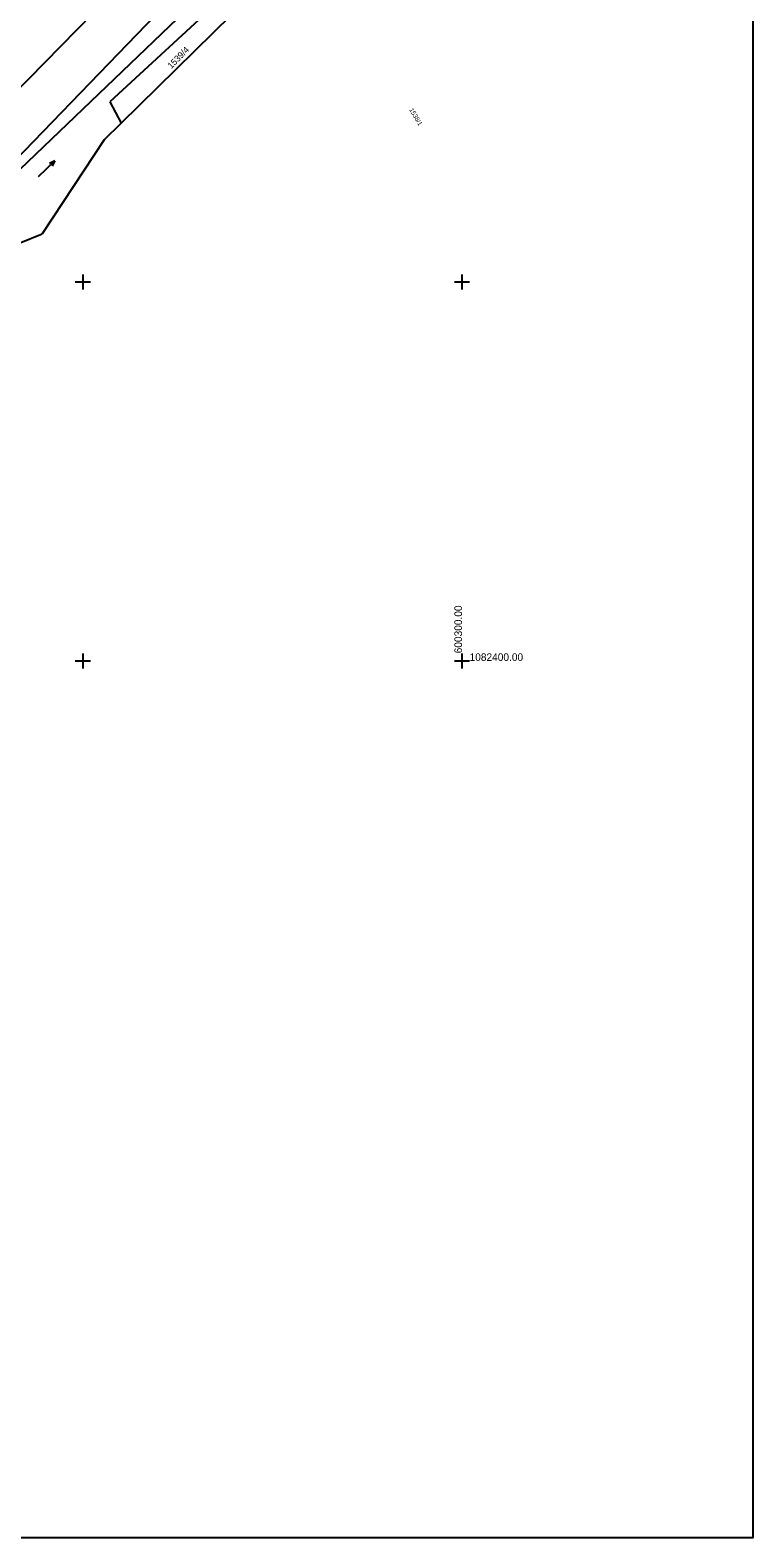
# Model space of a CAD drawing. Extents: x -601196 to -600262, y -1082523 to -1081922.
# Drawn here: x -600357 to -600261.6, y -1082515.7 to -1082316.8 of the extents above; entities that cross this region are included whole.
import ezdxf

# ---------------------------------------------------------------- set-up
doc = ezdxf.new("R2010")
doc.units = 0
for name, color, linetype in [('Vrstva 47', 7, 'Continuous'), ('Vrstva 59', 7, 'Continuous'), ('Vrstva 61', 7, 'Continuous'), ('Vrstva 63', 7, 'Continuous')]:
    doc.layers.add(name, color=color, linetype=linetype)

msp = doc.modelspace()

# ---------------------------------------------------------------- linework, layer by layer
at = {"layer": 'Vrstva 47'}
for p, q in [((-600420.14, -1082387.57), (-600313.5, -1082278.63)), ((-600321.42, -1082299.79), (-600375.67, -1082351.77)), ((-600320.22, -1082301.95), (-600346.46, -1082326.22)), ((-600344.96, -1082329.06), (-600320.08, -1082304.56)), ((-600333.37, -1082307.47), (-600365.05, -1082340.28)), ((-600346.46, -1082326.22), (-600344.96, -1082329.06)), ((-600347.2, -1082331.26), (-600344.96, -1082329.06)), ((-600347.2, -1082331.26), (-600355.38, -1082343.65)), ((-600355.85, -1082336.11), (-600353.71, -1082334.01)), ((-600353.71, -1082334.01), (-600354.42, -1082334.36)), ((-600353.71, -1082334.01), (-600354.07, -1082334.71)), ((-600366.11, -1082347.99), (-600355.38, -1082343.65))]:
    msp.add_line(p, q, dxfattribs=at)
at = {"layer": 'Vrstva 59'}
msp.add_lwpolyline([(-600681.64, -1082515.69), (-600681.64, -1081921.69), (-600261.64, -1081921.69), (-600261.64, -1082515.69)], close=True, dxfattribs=at)
at = {"layer": 'Vrstva 61'}
for p, q in [((-600351, -1082350), (-600349, -1082350)), ((-600351, -1082350), (-600349, -1082350)), ((-600350, -1082349), (-600350, -1082351)), ((-600350, -1082349), (-600350, -1082351)), ((-600301, -1082350), (-600299, -1082350)), ((-600301, -1082350), (-600299, -1082350)), ((-600300, -1082349), (-600300, -1082351)), ((-600300, -1082349), (-600300, -1082351)), ((-600350, -1082399), (-600350, -1082401)), ((-600300, -1082399), (-600300, -1082401)), ((-600351, -1082400), (-600349, -1082400)), ((-600301, -1082400), (-600299, -1082400))]:
    msp.add_line(p, q, dxfattribs=at)

# ---------------------------------------------------------------- texts
at = {"layer": 'Vrstva 47'}
for s, height, rotation, p in [('1539/4', 0.85, 45.9, (-600338.33, -1082321.95)), ('1538/1', 0.6, 300.6, (-600306.98, -1082327.28))]:
    msp.add_text(s, height=height, rotation=rotation, dxfattribs=at).set_placement(p)
at = {"layer": 'Vrstva 63'}
msp.add_text('600300.00', height=1, rotation=90, dxfattribs=at).set_placement((-600300, -1082399))
msp.add_text('1082400.00', height=1, dxfattribs=at).set_placement((-600299, -1082400))

doc.saveas('drawing.dxf')
